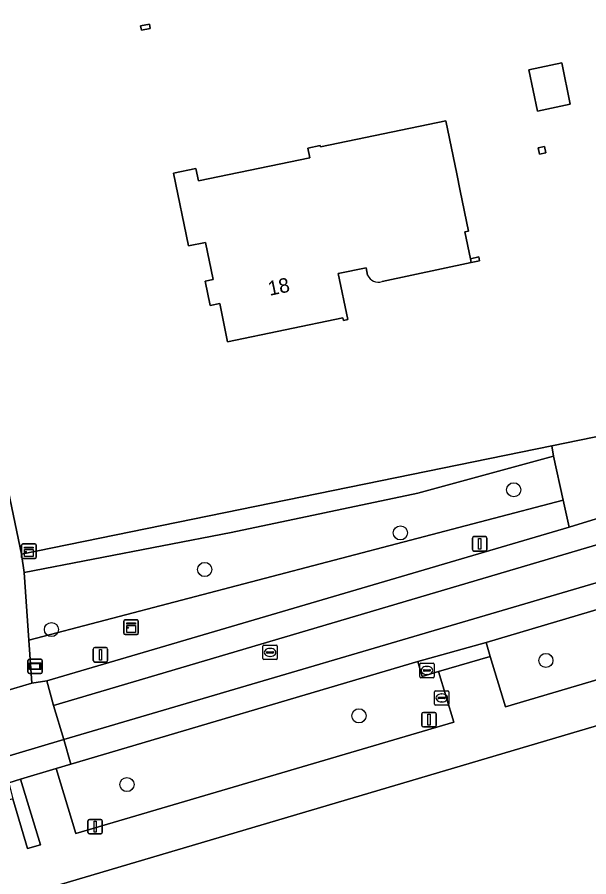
# Model space of a CAD drawing. Extents: x 162417 to 163722, y 384268 to 385417.
# Drawn here: x 163215.3 to 163254.9, y 384656 to 384715.4 of the extents above; entities that cross this region are included whole.
import ezdxf

# ---------------------------------------------------------------- set-up
doc = ezdxf.new("R2010")
doc.units = 0
for name, color, linetype in [('IMGEO_Boom', 7, 'Continuous'), ('IMGEO_Erf', 7, 'Continuous'), ('IMGEO_Groenvoorziening', 7, 'Continuous'), ('IMGEO_Haag', 7, 'Continuous'), ('IMGEO_Kast', 7, 'Continuous'), ('IMGEO_Kolk', 7, 'Continuous'), ('IMGEO_Lichtmast', 7, 'Continuous'), ('IMGEO_Muur', 7, 'Continuous'), ('IMGEO_Pand', 7, 'Continuous'), ('IMGEO_Pand_nummerreeks', 7, 'Continuous'), ('IMGEO_Rijbaan_lokaal_gesloten', 7, 'Continuous'), ('IMGEO_Rijbaan_lokaal_open', 7, 'Continuous'), ('IMGEO_Rioolput', 7, 'Continuous'), ('IMGEO_Voetpad_open', 7, 'Continuous'), ('IMGEO_Wegwijzer', 7, 'Continuous')]:
    doc.layers.add(name, color=color, linetype=linetype)

msp = doc.modelspace()

# ---------------------------------------------------------------- linework, layer by layer
at = {"layer": 'IMGEO_Boom'}
for centre in [(163249.675, 384682.735), (163241.835, 384679.753), (163228.302, 384677.22), (163217.707, 384673.066), (163251.902, 384670.927), (163238.971, 384667.097), (163222.929, 384662.346)]:
    msp.add_circle(centre, 0.489, dxfattribs=at)
at = {"layer": 'IMGEO_Erf'}
for points in [[(163175.984, 384894.871), (163189.317, 384805.604), (163189.37, 384805.252), (163225.47, 384820.661), (163226.246, 384820.995), (163226.612, 384820.203), (163229.945, 384812.987), (163225.751, 384811.048), (163227.566, 384807.013), (163229.658, 384807.895), (163230.655, 384805.678), (163228.563, 384804.796), (163224.144, 384802.92), (163192.437, 384789.411), (163200.664, 384750), (163215.633, 384678.291), (163252.312, 384685.775), (163256.147, 384686.557), (163258.646, 384687.067), (163309.002, 384702.202), (163311.14, 384702.845), (163432.284, 384738.586)], [(163239.572, 384697.588), (163239.475, 384698.099), (163237.539, 384697.697), (163238.201, 384694.51), (163237.895, 384694.447), (163237.857, 384694.629), (163229.891, 384692.975), (163229.342, 384695.615), (163228.682, 384695.478), (163228.333, 384697.158), (163228.888, 384697.273), (163228.352, 384699.853), (163227.175, 384699.609), (163226.141, 384704.649), (163227.693, 384704.971), (163227.873, 384704.106), (163235.565, 384705.703), (163235.425, 384706.379), (163236.286, 384706.557), (163236.307, 384706.456), (163244.973, 384708.255), (163245.733, 384704.596), (163245.979, 384703.413), (163246.556, 384700.63), (163246.295, 384700.576), (163246.68, 384698.723)], [(163246.68, 384698.723), (163247.253, 384698.842), (163247.307, 384698.584), (163246.734, 384698.461), (163240.571, 384697.135)], [(163310.764, 384635.802), (163312.926, 384636.415), (163300.634, 384677.935), (163300.352, 384678.47), (163299.946, 384679.602), (163217.164, 384655.09), (163211.589, 384653.439), (163162.154, 384638.801), (163163.733, 384633.465), (163163.883, 384632.961), (163162.442, 384632.589), (163160.726, 384632.111), (163162.281, 384626.769), (163162.11, 384626.271), (163182.33, 384558.292), (163182.739, 384554.615), (163182.929, 384552.906)]]:
    msp.add_lwpolyline(points, dxfattribs=at)
for points in [[(163224.481, 384714.954), (163224.542, 384714.65), (163223.925, 384714.525), (163223.864, 384714.829)], [(163250.725, 384711.789), (163252.996, 384712.261), (163253.588, 384709.41), (163251.317, 384708.938)], [(163251.888, 384706.042), (163251.458, 384705.95), (163251.368, 384706.381), (163251.798, 384706.473)]]:
    msp.add_lwpolyline(points, close=True, dxfattribs=at)
msp.add_arc((163240.324, 384697.918), 0.821, 203.68123, 287.53461, dxfattribs=at)
at = {"layer": 'IMGEO_Groenvoorziening'}
for points in [[(163252.434, 384685.061), (163252.312, 384685.775), (163215.633, 384678.291), (163215.822, 384677.004), (163230.136, 384679.777), (163243.043, 384682.506)], [(163253.099, 384682.014), (163252.434, 384685.061), (163243.043, 384682.506), (163230.136, 384679.777), (163215.822, 384677.004), (163216.145, 384672.327)], [(163253.504, 384680.159), (163253.099, 384682.014), (163216.145, 384672.327), (163216.351, 384669.353), (163217.379, 384669.518)], [(163266.1, 384672.742), (163265.056, 384676.225), (163263.975, 384675.897), (163263.667, 384676.895), (163247.767, 384672.179), (163248.057, 384671.212), (163249.111, 384667.719)], [(163245.534, 384666.668), (163244.471, 384670.163), (163243.346, 384669.828), (163243.04, 384670.847), (163219.046, 384663.763), (163218.038, 384663.465), (163219.395, 384658.96)], [(163216.049, 384657.922), (163216.941, 384658.171), (163215.573, 384662.717), (163214.749, 384662.457), (163215.04, 384661.365)]]:
    msp.add_lwpolyline(points, close=True, dxfattribs=at)
at = {"layer": 'IMGEO_Haag'}
msp.add_lwpolyline([(163243.043, 384682.506), (163252.434, 384685.061), (163252.312, 384685.775), (163215.633, 384678.291), (163215.822, 384677.004), (163230.136, 384679.777)], close=True, dxfattribs=at)
at = {"layer": 'IMGEO_Kast'}
for p, q in [((163215.645, 384678.061), (163215.645, 384678.902)), ((163215.645, 384678.902), (163215.645, 384678.061)), ((163215.72, 384678.986), (163216.561, 384678.986)), ((163216.561, 384678.986), (163215.72, 384678.986)), ((163216.645, 384678.911), (163216.645, 384678.07)), ((163216.645, 384678.07), (163216.645, 384678.911)), ((163216.57, 384677.986), (163215.729, 384677.986)), ((163215.729, 384677.986), (163216.57, 384677.986)), ((163222.713, 384672.807), (163222.713, 384673.648)), ((163222.713, 384673.648), (163222.713, 384672.807)), ((163222.788, 384673.732), (163223.629, 384673.732)), ((163223.629, 384673.732), (163222.788, 384673.732)), ((163223.713, 384673.657), (163223.713, 384672.816)), ((163223.713, 384672.816), (163223.713, 384673.657)), ((163223.638, 384672.732), (163222.797, 384672.732)), ((163222.797, 384672.732), (163223.638, 384672.732))]:
    msp.add_line(p, q, dxfattribs=at)
for points in [[(163215.84, 384678.776), (163216.44, 384678.776), (163216.44, 384678.691), (163215.84, 384678.691), (163215.84, 384678.776)], [(163215.84, 384678.601), (163216.44, 384678.601), (163216.44, 384678.112), (163215.84, 384678.112), (163215.84, 384678.601)], [(163222.908, 384673.522), (163223.508, 384673.522), (163223.508, 384673.437), (163222.908, 384673.437), (163222.908, 384673.522)], [(163222.908, 384673.347), (163223.508, 384673.347), (163223.508, 384672.858), (163222.908, 384672.858), (163222.908, 384673.347)]]:
    msp.add_lwpolyline(points, dxfattribs=at)
for centre in [(163215.924, 384678.45), (163222.992, 384673.196)]:
    msp.add_circle(centre, 0.0377, dxfattribs=at)
for centre, start, end in [((163215.723, 384678.908), 92.4484, 184.28452), ((163215.723, 384678.908), 92.4484, 184.28452), ((163216.567, 384678.908), 2.4484, 94.28452), ((163216.567, 384678.908), 2.4484, 94.28452), ((163215.723, 384678.064), 182.4484, 274.28452), ((163215.723, 384678.064), 182.4484, 274.28452), ((163216.567, 384678.064), 272.4484, 4.28452), ((163216.567, 384678.064), 272.4484, 4.28452), ((163222.791, 384673.654), 92.4484, 184.28452), ((163222.791, 384673.654), 92.4484, 184.28452), ((163223.635, 384673.654), 2.4484, 94.28452), ((163223.635, 384673.654), 2.4484, 94.28452), ((163222.791, 384672.81), 182.4484, 274.28452), ((163222.791, 384672.81), 182.4484, 274.28452), ((163223.635, 384672.81), 272.4484, 4.28452), ((163223.635, 384672.81), 272.4484, 4.28452)]:
    msp.add_arc(centre, 0.0779, start, end, dxfattribs=at)
at = {"layer": 'IMGEO_Kolk'}
for p, q in [((163243.173, 384669.811), (163243.173, 384670.663)), ((163243.248, 384670.737), (163244.1, 384670.737)), ((163244.174, 384670.663), (163244.174, 384669.811)), ((163243.432, 384670.231), (163243.432, 384670.243)), ((163243.87, 384670.194), (163243.472, 384670.194)), ((163243.475, 384670.28), (163243.873, 384670.28)), ((163243.684, 384669.957), (163243.659, 384669.957)), ((163243.661, 384670.517), (163243.686, 384670.517)), ((163243.916, 384670.243), (163243.916, 384670.231)), ((163244.1, 384669.737), (163243.248, 384669.737))]:
    msp.add_line(p, q, dxfattribs=at)
for points in [[(163243.173, 384669.811), (163243.173, 384670.663)], [(163243.248, 384670.737), (163244.1, 384670.737)], [(163244.174, 384670.663), (163244.174, 384669.811)], [(163244.1, 384669.737), (163243.248, 384669.737)]]:
    msp.add_lwpolyline(points, dxfattribs=at)
for centre, radius, start, end in [((163243.25, 384670.661), 0.0765, 91.55205, 178.44795), ((163243.25, 384670.661), 0.0765, 91.55205, 178.44795), ((163244.098, 384670.661), 0.0765, 1.55205, 88.44795), ((163244.098, 384670.661), 0.0765, 1.55205, 88.44795), ((163243.472, 384670.24), 0.0403, 85.87752, 175.75265), ((163243.469, 384670.23), 0.0366, 178.93798, 274.71019), ((163243.873, 384670.237), 0.043, 264.86636, 352.45326), ((163243.877, 384670.242), 0.0386, 1.73085, 96.63898), ((163243.25, 384669.813), 0.0765, 181.55205, 268.44795), ((163243.25, 384669.813), 0.0765, 181.55205, 268.44795), ((163244.098, 384669.813), 0.0765, 271.55205, 358.44795), ((163244.098, 384669.813), 0.0765, 271.55205, 358.44795)]:
    msp.add_arc(centre, radius, start, end, dxfattribs=at)
for centre, major_axis, ratio, start_param, end_param in [((163243.66, 384670.237), (-0.387, 0.002), 0.722429, 4.712389, 7.853982), ((163243.685, 384670.237), (-0.39, 0.002), 0.717154, 1.570796, 4.712389)]:
    msp.add_ellipse(centre, major_axis=major_axis, ratio=ratio, start_param=start_param, end_param=end_param, dxfattribs=at)
at = {"layer": 'IMGEO_Lichtmast'}
for p, q in [((163246.927, 384679.498), (163247.717, 384679.498)), ((163247.717, 384679.498), (163246.927, 384679.498)), ((163246.827, 384678.598), (163246.827, 384679.398)), ((163246.827, 384679.398), (163246.827, 384678.598)), ((163247.817, 384679.398), (163247.817, 384678.598)), ((163247.817, 384678.598), (163247.817, 384679.398)), ((163247.717, 384678.498), (163246.927, 384678.498)), ((163246.927, 384678.498), (163247.717, 384678.498)), ((163220.7, 384671.82), (163221.49, 384671.82)), ((163221.49, 384671.82), (163220.7, 384671.82)), ((163220.6, 384670.92), (163220.6, 384671.72)), ((163220.6, 384671.72), (163220.6, 384670.92)), ((163221.59, 384671.72), (163221.59, 384670.92)), ((163221.59, 384670.92), (163221.59, 384671.72)), ((163221.49, 384670.82), (163220.7, 384670.82)), ((163220.7, 384670.82), (163221.49, 384670.82)), ((163243.325, 384666.429), (163243.325, 384667.229)), ((163243.325, 384667.229), (163243.325, 384666.429)), ((163243.425, 384667.329), (163244.215, 384667.329)), ((163244.215, 384667.329), (163243.425, 384667.329)), ((163244.315, 384667.229), (163244.315, 384666.429)), ((163244.315, 384666.429), (163244.315, 384667.229)), ((163244.215, 384666.329), (163243.425, 384666.329)), ((163243.425, 384666.329), (163244.215, 384666.329)), ((163220.332, 384659.936), (163221.122, 384659.936)), ((163221.122, 384659.936), (163220.332, 384659.936)), ((163220.232, 384659.036), (163220.232, 384659.836)), ((163220.232, 384659.836), (163220.232, 384659.036)), ((163221.222, 384659.836), (163221.222, 384659.036)), ((163221.222, 384659.036), (163221.222, 384659.836)), ((163221.122, 384658.936), (163220.332, 384658.936)), ((163220.332, 384658.936), (163221.122, 384658.936))]:
    msp.add_line(p, q, dxfattribs=at)
for points in [[(163247.247, 384679.373), (163247.397, 384679.373), (163247.397, 384678.623), (163247.247, 384678.623), (163247.247, 384679.373)], [(163221.02, 384671.695), (163221.17, 384671.695), (163221.17, 384670.945), (163221.02, 384670.945), (163221.02, 384671.695)], [(163243.745, 384667.204), (163243.895, 384667.204), (163243.895, 384666.454), (163243.745, 384666.454), (163243.745, 384667.204)], [(163220.652, 384659.811), (163220.802, 384659.811), (163220.802, 384659.061), (163220.652, 384659.061), (163220.652, 384659.811)]]:
    msp.add_lwpolyline(points, dxfattribs=at)
for centre, start, end in [((163246.927, 384679.398), 90, 180), ((163246.927, 384679.398), 90, 180), ((163247.717, 384679.398), 0, 90), ((163247.717, 384679.398), 360, 90), ((163246.927, 384678.598), 180, 270), ((163246.927, 384678.598), 180, 270), ((163247.717, 384678.598), 270, 0), ((163247.717, 384678.598), 270, 0), ((163220.7, 384671.72), 90, 180), ((163220.7, 384671.72), 90, 180), ((163221.49, 384671.72), 0, 90), ((163221.49, 384671.72), 360, 90), ((163220.7, 384670.92), 180, 270), ((163220.7, 384670.92), 180, 270), ((163221.49, 384670.92), 270, 0), ((163221.49, 384670.92), 270, 0), ((163243.425, 384667.229), 90, 180), ((163243.425, 384667.229), 90, 180), ((163244.215, 384667.229), 0, 90), ((163244.215, 384667.229), 360, 90), ((163243.425, 384666.429), 180, 270), ((163243.425, 384666.429), 180, 270), ((163244.215, 384666.429), 270, 0), ((163244.215, 384666.429), 270, 0), ((163220.332, 384659.836), 90, 180), ((163220.332, 384659.836), 90, 180), ((163221.122, 384659.836), 0, 90), ((163221.122, 384659.836), 360, 90), ((163220.332, 384659.036), 180, 270), ((163220.332, 384659.036), 180, 270), ((163221.122, 384659.036), 270, 0), ((163221.122, 384659.036), 270, 0)]:
    msp.add_arc(centre, 0.1, start, end, dxfattribs=at)
at = {"layer": 'IMGEO_Muur'}
msp.add_lwpolyline([(163246.68, 384698.723), (163246.734, 384698.461), (163247.307, 384698.584), (163247.253, 384698.842)], close=True, dxfattribs=at)
at = {"layer": 'IMGEO_Pand'}
for points in [[(163224.481, 384714.954), (163223.864, 384714.829), (163223.925, 384714.525), (163224.542, 384714.65)], [(163250.725, 384711.789), (163251.317, 384708.938), (163253.588, 384709.41), (163252.996, 384712.261)], [(163251.888, 384706.042), (163251.798, 384706.473), (163251.368, 384706.381), (163251.458, 384705.95)]]:
    msp.add_lwpolyline(points, close=True, dxfattribs=at)
msp.add_lwpolyline([(163240.571, 384697.135), (163246.734, 384698.461), (163246.68, 384698.723), (163246.295, 384700.576), (163246.556, 384700.63), (163245.979, 384703.413), (163245.733, 384704.596), (163244.973, 384708.255), (163236.307, 384706.456), (163236.286, 384706.557), (163235.425, 384706.379), (163235.565, 384705.703), (163227.873, 384704.106), (163227.693, 384704.971), (163226.141, 384704.649), (163227.175, 384699.609), (163228.352, 384699.853), (163228.888, 384697.273), (163228.333, 384697.158), (163228.682, 384695.478), (163229.342, 384695.615), (163229.891, 384692.975), (163237.857, 384694.629), (163237.895, 384694.447), (163238.201, 384694.51), (163237.539, 384697.697), (163239.475, 384698.099), (163239.572, 384697.588)], dxfattribs=at)
msp.add_arc((163240.324, 384697.918), 0.821, 203.68123, 287.53461, dxfattribs=at)
at = {"layer": 'IMGEO_Rijbaan_lokaal_gesloten'}
for points in [[(163257.233, 384681.296), (163253.504, 384680.159), (163217.379, 384669.518), (163217.858, 384667.814), (163289.922, 384689.131), (163289.436, 384690.763)], [(163219.046, 384663.763), (163243.04, 384670.847), (163247.767, 384672.179), (163263.667, 384676.895), (163268.396, 384678.308), (163274.226, 384680.026), (163284.314, 384682.93), (163291.154, 384684.983), (163290.633, 384686.675), (163218.569, 384665.465)], [(163199.805, 384658.057), (163205.26, 384659.627), (163210.145, 384661.119), (163214.749, 384662.457), (163215.573, 384662.717), (163218.038, 384663.465), (163219.046, 384663.763), (163218.569, 384665.465), (163199.311, 384659.719)]]:
    msp.add_lwpolyline(points, close=True, dxfattribs=at)
at = {"layer": 'IMGEO_Rijbaan_lokaal_open'}
msp.add_lwpolyline([(163218.569, 384665.465), (163290.633, 384686.675), (163289.922, 384689.131), (163217.858, 384667.814)], close=True, dxfattribs=at)
msp.add_lwpolyline([(163199.163, 384664.143), (163198.09, 384663.826), (163198.603, 384662.094), (163199.311, 384659.719), (163218.569, 384665.465), (163217.858, 384667.814), (163217.379, 384669.518), (163216.351, 384669.353), (163213.831, 384668.612)], dxfattribs=at)
at = {"layer": 'IMGEO_Rioolput'}
for p, q in [((163232.325, 384671.059), (163232.325, 384671.911)), ((163232.4, 384671.985), (163233.252, 384671.985)), ((163232.813, 384671.765), (163232.838, 384671.765)), ((163233.326, 384671.911), (163233.326, 384671.059)), ((163232.584, 384671.479), (163232.584, 384671.491)), ((163233.022, 384671.442), (163232.624, 384671.442)), ((163232.627, 384671.528), (163233.025, 384671.528)), ((163232.836, 384671.205), (163232.811, 384671.205)), ((163233.068, 384671.491), (163233.068, 384671.479)), ((163233.252, 384670.985), (163232.4, 384670.985)), ((163244.271, 384668.835), (163245.123, 384668.835)), ((163244.196, 384667.909), (163244.196, 384668.761)), ((163244.455, 384668.329), (163244.455, 384668.341)), ((163244.893, 384668.292), (163244.495, 384668.292)), ((163244.498, 384668.378), (163244.896, 384668.378)), ((163244.684, 384668.615), (163244.709, 384668.615)), ((163244.939, 384668.341), (163244.939, 384668.329)), ((163245.197, 384668.761), (163245.197, 384667.909)), ((163245.123, 384667.835), (163244.271, 384667.835)), ((163244.707, 384668.055), (163244.682, 384668.055))]:
    msp.add_line(p, q, dxfattribs=at)
for points in [[(163232.325, 384671.059), (163232.325, 384671.911)], [(163232.4, 384671.985), (163233.252, 384671.985)], [(163233.326, 384671.911), (163233.326, 384671.059)], [(163233.252, 384670.985), (163232.4, 384670.985)], [(163244.271, 384668.835), (163245.123, 384668.835)], [(163244.196, 384667.909), (163244.196, 384668.761)], [(163245.197, 384668.761), (163245.197, 384667.909)], [(163245.123, 384667.835), (163244.271, 384667.835)]]:
    msp.add_lwpolyline(points, dxfattribs=at)
for centre, radius, start, end in [((163232.402, 384671.909), 0.0765, 91.55205, 178.44795), ((163232.402, 384671.909), 0.0765, 91.55205, 178.44795), ((163233.25, 384671.909), 0.0765, 1.55205, 88.44795), ((163233.25, 384671.909), 0.0765, 1.55205, 88.44795), ((163232.624, 384671.488), 0.0403, 85.87752, 175.75265), ((163232.621, 384671.478), 0.0366, 178.93798, 274.71019), ((163233.025, 384671.485), 0.043, 264.86636, 352.45326), ((163233.029, 384671.49), 0.0386, 1.73085, 96.63898), ((163232.402, 384671.061), 0.0765, 181.55205, 268.44795), ((163232.402, 384671.061), 0.0765, 181.55205, 268.44795), ((163233.25, 384671.061), 0.0765, 271.55205, 358.44795), ((163233.25, 384671.061), 0.0765, 271.55205, 358.44795), ((163244.273, 384668.759), 0.0765, 91.55205, 178.44795), ((163244.273, 384668.759), 0.0765, 91.55205, 178.44795), ((163245.121, 384668.759), 0.0765, 1.55205, 88.44795), ((163245.121, 384668.759), 0.0765, 1.55205, 88.44795), ((163244.495, 384668.338), 0.0403, 85.87752, 175.75265), ((163244.492, 384668.328), 0.0366, 178.93798, 274.71019), ((163244.896, 384668.335), 0.043, 264.86636, 352.45326), ((163244.9, 384668.34), 0.0386, 1.73085, 96.63898), ((163244.273, 384667.911), 0.0765, 181.55205, 268.44795), ((163244.273, 384667.911), 0.0765, 181.55205, 268.44795), ((163245.121, 384667.911), 0.0765, 271.55205, 358.44795), ((163245.121, 384667.911), 0.0765, 271.55205, 358.44795)]:
    msp.add_arc(centre, radius, start, end, dxfattribs=at)
for centre, major_axis, ratio, start_param, end_param in [((163232.812, 384671.485), (-0.387, 0.002), 0.722429, 4.712389, 7.853982), ((163232.837, 384671.485), (-0.39, 0.002), 0.717154, 1.570796, 4.712389), ((163244.683, 384668.335), (-0.387, 0.002), 0.722429, 4.712389, 7.853982), ((163244.708, 384668.335), (-0.39, 0.002), 0.717154, 1.570796, 4.712389)]:
    msp.add_ellipse(centre, major_axis=major_axis, ratio=ratio, start_param=start_param, end_param=end_param, dxfattribs=at)
at = {"layer": 'IMGEO_Voetpad_open'}
for points in [[(163202.624, 384726.782), (163212.911, 384677.77), (163213.416, 384675.345), (163213.831, 384668.612), (163216.351, 384669.353), (163216.145, 384672.327), (163215.822, 384677.004), (163215.633, 384678.291), (163200.664, 384750)], [(163217.164, 384655.09), (163299.946, 384679.602)], [(163266.1, 384672.742), (163249.111, 384667.719), (163248.057, 384671.212), (163244.471, 384670.163), (163245.534, 384666.668), (163219.395, 384658.96), (163218.038, 384663.465), (163215.573, 384662.717), (163216.941, 384658.171), (163216.049, 384657.922), (163215.04, 384661.365), (163211.624, 384660.318), (163212.618, 384656.917), (163206.554, 384655.12), (163205.547, 384658.562), (163202.076, 384657.539), (163203.103, 384654.103)]]:
    msp.add_lwpolyline(points, dxfattribs=at)
for points in [[(163256.147, 384686.557), (163252.312, 384685.775), (163252.434, 384685.061), (163253.099, 384682.014), (163253.504, 384680.159), (163257.233, 384681.296), (163256.857, 384683.119)], [(163243.04, 384670.847), (163243.346, 384669.828), (163244.471, 384670.163), (163248.057, 384671.212), (163247.767, 384672.179)]]:
    msp.add_lwpolyline(points, close=True, dxfattribs=at)
at = {"layer": 'IMGEO_Wegwijzer'}
for p, q in [((163216.082, 384670.125), (163216.082, 384670.925)), ((163216.082, 384670.925), (163216.082, 384670.125)), ((163216.182, 384671.025), (163216.972, 384671.025)), ((163216.972, 384671.025), (163216.182, 384671.025)), ((163217.072, 384670.925), (163217.072, 384670.125)), ((163217.072, 384670.125), (163217.072, 384670.925)), ((163216.972, 384670.025), (163216.182, 384670.025)), ((163216.182, 384670.025), (163216.972, 384670.025))]:
    msp.add_line(p, q, dxfattribs=at)
for points in [[(163216.183, 384670.757), (163216.971, 384670.757), (163216.971, 384670.293), (163216.183, 384670.293), (163216.183, 384670.757)], [(163216.248, 384670.692), (163216.248, 384670.358), (163216.906, 384670.358), (163216.906, 384670.692), (163216.248, 384670.692)]]:
    msp.add_lwpolyline(points, dxfattribs=at)
for centre, start, end in [((163216.182, 384670.925), 90, 180), ((163216.182, 384670.925), 90, 180), ((163216.972, 384670.925), 0, 90), ((163216.972, 384670.925), 360, 90), ((163216.182, 384670.125), 180, 270), ((163216.182, 384670.125), 180, 270), ((163216.972, 384670.125), 270, 0), ((163216.972, 384670.125), 270, 0)]:
    msp.add_arc(centre, 0.1, start, end, dxfattribs=at)

# ---------------------------------------------------------------- texts
at = {"layer": 'IMGEO_Pand_nummerreeks'}
msp.add_text('18', height=1, rotation=11.72845, dxfattribs=at).set_placement((163232.797, 384696.152))

doc.saveas('drawing.dxf')
